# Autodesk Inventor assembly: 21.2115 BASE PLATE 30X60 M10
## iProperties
Created: 2012-10
Part Number: 21.2115 BASE PLATE 30X60 M10
Document SubType Name: Assembly
Designer: Administrator
Author: Administrator
